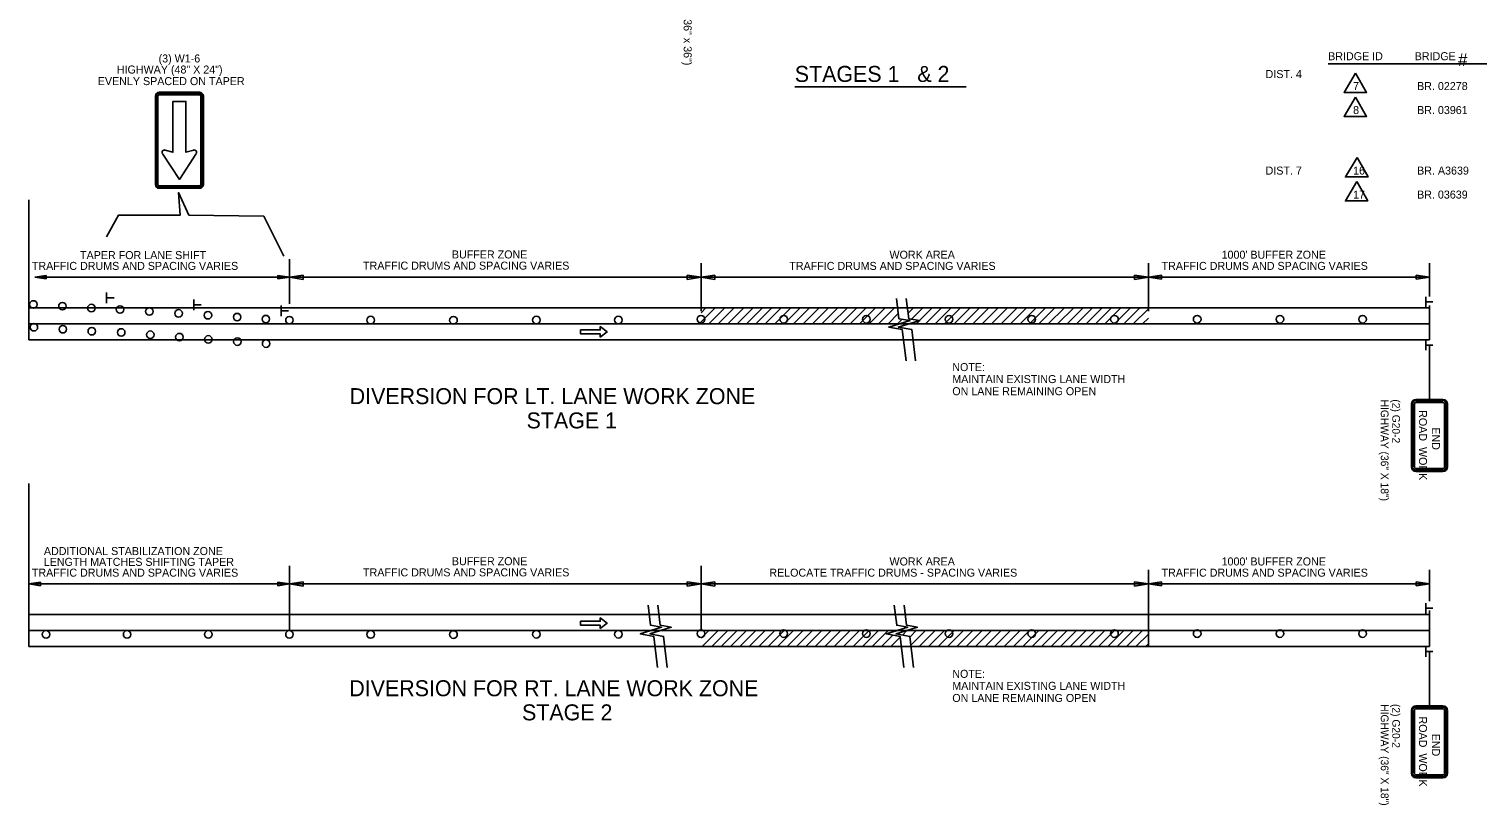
# Model space of a CAD drawing. Extents: x 1930579 to 1937521, y 596183 to 597566.
# Drawn here: x 1935116 to 1936202, y 596334 to 596916 of the extents above; entities that cross this region are included whole.
import ezdxf

# ---------------------------------------------------------------- set-up
doc = ezdxf.new("R2010")
doc.units = 0
for name, color, linetype in [('Default', 7, 'Continuous'), ('P_TC_Signs_Permanent', 7, 'Continuous'), ('P_TC_Signs_Temporary', 7, 'Continuous'), ('R_Annotation', 7, 'Continuous'), ('R_Striping', 7, 'Continuous')]:
    doc.layers.add(name, color=color, linetype=linetype)

msp = doc.modelspace()

# ---------------------------------------------------------------- linework, layer by layer
at = {"layer": 'Default'}
for p, q in [((1935690.4, 596872.5), (1935818.8, 596872.5)), ((1935116.2, 596787.6), (1935116.2, 596682.7)), ((1935311.5, 596743.1), (1935311.5, 596709.7)), ((1935620.1, 596740.1), (1935620.1, 596704.2)), ((1935955.5, 596740.1), (1935955.5, 596704.2)), ((1936166.2, 596740.1), (1936166.2, 596715.1)), ((1935120.5, 596729.6), (1935129.2, 596730.9)), ((1935311.5, 596729.6), (1935120.5, 596729.6)), ((1935129.2, 596728.3), (1935120.5, 596729.6)), ((1935129.2, 596730.9), (1935129.2, 596728.3)), ((1935302.8, 596728.3), (1935302.8, 596730.9)), ((1935302.8, 596730.9), (1935311.5, 596729.6)), ((1935311.5, 596729.6), (1935302.8, 596728.3)), ((1935620.1, 596729.6), (1935311.5, 596729.6)), ((1935311.6, 596729.6), (1935321.9, 596731.1)), ((1935321.9, 596728), (1935311.6, 596729.6)), ((1935321.9, 596731.1), (1935321.9, 596728)), ((1935609.8, 596728), (1935609.8, 596731.1)), ((1935609.8, 596731.1), (1935620.1, 596729.6)), ((1935620.1, 596729.6), (1935609.8, 596728)), ((1935620.1, 596729.6), (1935630.4, 596731.1)), ((1935955.5, 596729.6), (1935620.1, 596729.6)), ((1935630.4, 596728), (1935620.1, 596729.6)), ((1935630.4, 596731.1), (1935630.4, 596728)), ((1935945.2, 596728), (1935945.2, 596731.1)), ((1935945.2, 596731.1), (1935955.5, 596729.6)), ((1935955.5, 596729.6), (1935945.2, 596728)), ((1935955.5, 596729.6), (1935965.4, 596731.1)), ((1936166.2, 596729.6), (1935955.5, 596729.6)), ((1935965.4, 596728.1), (1935955.5, 596729.6)), ((1935965.4, 596731.1), (1935965.4, 596728.1)), ((1936156.3, 596728.1), (1936156.3, 596731.1)), ((1936156.3, 596731.1), (1936166.2, 596729.6)), ((1936156.3, 596728.1), (1936156.3, 596731.1)), ((1936156.3, 596731.1), (1936166.2, 596729.6)), ((1936166.2, 596729.6), (1936156.3, 596728.1)), ((1936166.2, 596729.6), (1936156.3, 596728.1)), ((1935174.4, 596710.2), (1935174.4, 596718.2)), ((1936166.2, 596706.7), (1935116.2, 596706.7)), ((1935174.5, 596714.2), (1935180, 596714.2)), ((1935239.8, 596704.8), (1935239.8, 596712.8)), ((1935239.9, 596708.8), (1935245.4, 596708.8)), ((1935305.4, 596700.3), (1935305.4, 596708.3)), ((1935305.5, 596704.3), (1935310.9, 596704.3)), ((1935618.8, 596694.7), (1935630.8, 596706.7)), ((1935620.1, 596703), (1935623.8, 596706.7)), ((1935625.9, 596694.7), (1935637.9, 596706.7)), ((1935633, 596694.7), (1935645, 596706.7)), ((1935640.1, 596694.7), (1935652.1, 596706.7)), ((1935647.1, 596694.7), (1935659.1, 596706.7)), ((1935654.2, 596694.7), (1935666.2, 596706.7)), ((1935661.3, 596694.7), (1935673.3, 596706.7)), ((1935668.3, 596694.7), (1935680.3, 596706.7)), ((1935675.4, 596694.7), (1935687.4, 596706.7)), ((1935682.5, 596694.7), (1935694.5, 596706.7)), ((1935689.5, 596694.7), (1935701.5, 596706.7)), ((1935696.6, 596694.7), (1935708.6, 596706.7)), ((1935703.7, 596694.7), (1935715.7, 596706.7)), ((1935710.8, 596694.7), (1935722.8, 596706.7)), ((1935717.8, 596694.7), (1935729.8, 596706.7)), ((1935724.9, 596694.7), (1935736.9, 596706.7)), ((1935732, 596694.7), (1935744, 596706.7)), ((1935739, 596694.7), (1935751, 596706.7)), ((1935746.1, 596694.7), (1935758.1, 596706.7)), ((1935753.2, 596694.7), (1935765.2, 596706.7)), ((1935775.3, 596702.6), (1935779.3, 596706.7)), ((1935777.9, 596698.2), (1935786.4, 596706.7)), ((1935783.9, 596697.1), (1935793.5, 596706.7)), ((1935788.5, 596694.7), (1935800.5, 596706.7)), ((1935795.6, 596694.7), (1935807.6, 596706.7)), ((1935802.7, 596694.7), (1935814.7, 596706.7)), ((1935809.8, 596694.7), (1935821.8, 596706.7)), ((1935816.8, 596694.7), (1935828.8, 596706.7)), ((1935823.9, 596694.7), (1935835.9, 596706.7)), ((1935831, 596694.7), (1935843, 596706.7)), ((1935838, 596694.7), (1935850, 596706.7)), ((1935845.1, 596694.7), (1935857.1, 596706.7)), ((1935852.2, 596694.7), (1935864.2, 596706.7)), ((1935859.3, 596694.7), (1935871.3, 596706.7)), ((1935866.3, 596694.7), (1935878.3, 596706.7)), ((1935873.4, 596694.7), (1935885.4, 596706.7)), ((1935880.5, 596694.7), (1935892.5, 596706.7)), ((1935887.5, 596694.7), (1935899.5, 596706.7)), ((1935894.6, 596694.7), (1935906.6, 596706.7)), ((1935901.7, 596694.7), (1935913.7, 596706.7)), ((1935908.8, 596694.7), (1935920.8, 596706.7)), ((1935915.8, 596694.7), (1935927.8, 596706.7)), ((1935922.9, 596694.7), (1935934.9, 596706.7)), ((1935930, 596694.7), (1935942, 596706.7)), ((1935937, 596694.7), (1935949, 596706.7)), ((1935944.1, 596694.7), (1935955.5, 596706)), ((1936163.5, 596714.9), (1936163.5, 596707.3)), ((1936163.6, 596711.1), (1936168.8, 596711.1)), ((1936166.2, 596708.4), (1936166.2, 596682.7)), ((1935116.2, 596694.7), (1936166.2, 596694.7)), ((1935760.3, 596694.7), (1935768, 596702.4)), ((1935767.3, 596694.7), (1935770.8, 596698.1)), ((1935781.5, 596694.7), (1935783.8, 596697)), ((1935951.2, 596694.7), (1935955.5, 596699)), ((1935116.2, 596682.7), (1935396.7, 596682.7)), ((1936166.2, 596682.7), (1935116.2, 596682.7)), ((1935380.8, 596682.7), (1935655.9, 596682.7)), ((1935593.2, 596682.7), (1935619.9, 596682.7)), ((1935619.9, 596682.7), (1935770.5, 596682.7)), ((1935778.2, 596682.7), (1935955.5, 596682.7)), ((1936163.5, 596682.4), (1936163.5, 596674.8)), ((1936163.6, 596678.6), (1936168.8, 596678.6)), ((1935116.2, 596574.9), (1935116.2, 596452.6)), ((1935311.5, 596513), (1935311.5, 596464.6)), ((1935620.1, 596513), (1935620.1, 596474.1)), ((1935620.1, 596513), (1935620.1, 596464.6)), ((1935955.5, 596510), (1935955.5, 596452.6)), ((1935955.5, 596510), (1935955.5, 596474.1)), ((1936166.2, 596510), (1936166.2, 596486.5)), ((1935116.2, 596499.5), (1935124.9, 596500.8)), ((1935311.5, 596499.5), (1935116.2, 596499.5)), ((1935124.9, 596498.2), (1935116.2, 596499.5)), ((1935124.9, 596500.8), (1935124.9, 596498.2)), ((1935302.8, 596498.2), (1935302.8, 596500.8)), ((1935302.8, 596500.8), (1935311.5, 596499.5)), ((1935311.5, 596499.5), (1935302.8, 596498.2)), ((1935620.1, 596499.5), (1935311.5, 596499.5)), ((1935311.6, 596499.5), (1935321.9, 596501)), ((1935321.9, 596497.9), (1935311.6, 596499.5)), ((1935321.9, 596501), (1935321.9, 596497.9)), ((1935609.8, 596497.9), (1935609.8, 596501)), ((1935609.8, 596501), (1935620.1, 596499.5)), ((1935620.1, 596499.5), (1935609.8, 596497.9)), ((1935620.1, 596499.5), (1935630.4, 596501)), ((1935955.5, 596499.5), (1935620.1, 596499.5)), ((1935630.4, 596497.9), (1935620.1, 596499.5)), ((1935630.4, 596501), (1935630.4, 596497.9)), ((1935945.2, 596497.9), (1935945.2, 596501)), ((1935945.2, 596501), (1935955.5, 596499.5)), ((1935955.5, 596499.5), (1935945.2, 596497.9)), ((1935955.5, 596499.5), (1935965.4, 596501)), ((1936166.2, 596499.5), (1935955.5, 596499.5)), ((1935965.4, 596498), (1935955.5, 596499.5)), ((1935965.4, 596501), (1935965.4, 596498)), ((1936156.3, 596498), (1936156.3, 596501)), ((1936156.3, 596501), (1936166.2, 596499.5)), ((1936156.3, 596498), (1936156.3, 596501)), ((1936156.3, 596501), (1936166.2, 596499.5)), ((1936166.2, 596499.5), (1936156.3, 596498)), ((1936166.2, 596499.5), (1936156.3, 596498)), ((1936166.2, 596476.6), (1935116.2, 596476.6)), ((1936163.5, 596485.1), (1936163.5, 596477.4)), ((1936163.6, 596481.3), (1936168.8, 596481.3)), ((1936166.2, 596479.5), (1936166.2, 596452.6)), ((1935116.2, 596464.6), (1936166.2, 596464.6)), ((1935620.1, 596458.8), (1935625.9, 596464.6)), ((1935621, 596452.6), (1935633, 596464.6)), ((1935628.1, 596452.6), (1935640.1, 596464.6)), ((1935635.1, 596452.6), (1935647.1, 596464.6)), ((1935642.2, 596452.6), (1935654.2, 596464.6)), ((1935649.3, 596452.6), (1935661.3, 596464.6)), ((1935656.3, 596452.6), (1935668.3, 596464.6)), ((1935663.4, 596452.6), (1935675.4, 596464.6)), ((1935670.5, 596452.6), (1935682.5, 596464.6)), ((1935677.5, 596452.6), (1935689.5, 596464.6)), ((1935684.6, 596452.6), (1935696.6, 596464.6)), ((1935691.7, 596452.6), (1935703.7, 596464.6)), ((1935698.8, 596452.6), (1935710.8, 596464.6)), ((1935705.8, 596452.6), (1935717.8, 596464.6)), ((1935712.9, 596452.6), (1935724.9, 596464.6)), ((1935720, 596452.6), (1935732, 596464.6)), ((1935727, 596452.6), (1935739, 596464.6)), ((1935734.1, 596452.6), (1935746.1, 596464.6)), ((1935741.2, 596452.6), (1935753.2, 596464.6)), ((1935748.3, 596452.6), (1935760.3, 596464.6)), ((1935755.3, 596452.6), (1935764, 596461.2)), ((1935762.4, 596452.6), (1935769.4, 596459.6)), ((1935771.1, 596461.2), (1935774.4, 596464.6)), ((1935776.5, 596452.6), (1935788.5, 596464.6)), ((1935776.6, 596459.7), (1935781.5, 596464.6)), ((1935783.6, 596452.6), (1935795.6, 596464.6)), ((1935790.7, 596452.6), (1935802.7, 596464.6)), ((1935797.8, 596452.6), (1935809.8, 596464.6)), ((1935804.8, 596452.6), (1935816.8, 596464.6)), ((1935811.9, 596452.6), (1935823.9, 596464.6)), ((1935819, 596452.6), (1935831, 596464.6)), ((1935826, 596452.6), (1935838, 596464.6)), ((1935833.1, 596452.6), (1935845.1, 596464.6)), ((1935840.2, 596452.6), (1935852.2, 596464.6)), ((1935847.3, 596452.6), (1935859.3, 596464.6)), ((1935854.3, 596452.6), (1935866.3, 596464.6)), ((1935861.4, 596452.6), (1935873.4, 596464.6)), ((1935868.5, 596452.6), (1935880.5, 596464.6)), ((1935875.5, 596452.6), (1935887.5, 596464.6)), ((1935882.6, 596452.6), (1935894.6, 596464.6)), ((1935889.7, 596452.6), (1935901.7, 596464.6)), ((1935896.8, 596452.6), (1935908.8, 596464.6)), ((1935903.8, 596452.6), (1935915.8, 596464.6)), ((1935910.9, 596452.6), (1935922.9, 596464.6)), ((1935918, 596452.6), (1935930, 596464.6)), ((1935925, 596452.6), (1935937, 596464.6)), ((1935932.1, 596452.6), (1935944.1, 596464.6)), ((1935939.2, 596452.6), (1935951.2, 596464.6)), ((1935946.2, 596452.6), (1935955.5, 596461.8)), ((1935953.3, 596452.6), (1935955.5, 596454.7)), ((1935116.2, 596452.6), (1935396.7, 596452.6)), ((1936166.2, 596452.6), (1935116.2, 596452.6)), ((1935380.8, 596452.6), (1935655.9, 596452.6)), ((1935593.2, 596452.6), (1935619.9, 596452.6)), ((1935619.9, 596452.6), (1935770.5, 596452.6)), ((1935769.5, 596452.6), (1935770.1, 596453.2)), ((1935778.2, 596452.6), (1935955.5, 596452.6)), ((1936163.5, 596452.6), (1936163.5, 596444.9)), ((1936163.6, 596448.8), (1936168.8, 596448.8))]:
    msp.add_line(p, q, dxfattribs=at)
for points in [[(1935766.6, 596713.6), (1935768.5, 596698.5), (1935776.8, 596697.1), (1935760.8, 596692.2), (1935770.9, 596690.3), (1935773.8, 596666.9)], [(1935773.9, 596713.6), (1935775.8, 596698.5), (1935784.1, 596697.1), (1935768, 596692.2), (1935778.2, 596690.3), (1935781, 596666.9)], [(1935580.4, 596483.5), (1935582.3, 596468.5), (1935590.5, 596467), (1935574.5, 596462.1), (1935584.7, 596460.2), (1935587.5, 596436.8)], [(1935587.7, 596483.5), (1935589.5, 596468.5), (1935597.8, 596467), (1935581.8, 596462.1), (1935592, 596460.2), (1935594.8, 596436.8)], [(1935765, 596483.5), (1935766.9, 596468.5), (1935775.1, 596467), (1935759.1, 596462.1), (1935769.3, 596460.2), (1935772.1, 596436.8)], [(1935772.3, 596483.5), (1935774.2, 596468.5), (1935782.4, 596467), (1935766.4, 596462.1), (1935776.6, 596460.2), (1935779.4, 596436.8)]]:
    msp.add_lwpolyline(points, dxfattribs=at)
for centre, radius in [((1935119.5, 596709.2), 2.81), ((1935141.3, 596707.9), 2.81), ((1935163, 596706.5), 2.81), ((1935184.5, 596705.4), 2.81), ((1935206.5, 596703.9), 2.81), ((1935228.4, 596702.5), 2.81), ((1935119.9, 596692.1), 2.81), ((1935141.6, 596690.6), 2.81), ((1935250.4, 596701.1), 2.81), ((1935272.3, 596699.7), 2.81), ((1935293.8, 596698.2), 2.81), ((1935311.5, 596697.4), 2.81), ((1935372.4, 596697.4), 2.87), ((1935434.5, 596697.3), 2.87), ((1935496.7, 596697.5), 2.87), ((1935558.2, 596697.5), 2.87), ((1935620.1, 596698.1), 2.87), ((1935682.1, 596698.1), 2.87), ((1935744.1, 596698.1), 2.87), ((1935806.1, 596698.1), 2.87), ((1935868.1, 596698.1), 2.87), ((1935930.1, 596698.1), 2.87), ((1935992.1, 596698.1), 2.87), ((1936054.1, 596698.1), 2.87), ((1936116.1, 596698.1), 2.87), ((1935163.3, 596689.1), 2.81), ((1935185.4, 596688.2), 2.81), ((1935207.2, 596686.5), 2.81), ((1935229, 596684.7), 2.81), ((1935250.7, 596683), 2.81), ((1935272.5, 596681.3), 2.81), ((1935294, 596679.8), 2.81), ((1935129, 596461.7), 2.81), ((1935189.8, 596461.7), 2.81), ((1935250.7, 596461.7), 2.81), ((1935311.5, 596461.7), 2.81), ((1935372.4, 596461.7), 2.87), ((1935434.5, 596461.6), 2.87), ((1935496.7, 596461.8), 2.87), ((1935558.2, 596461.8), 2.87), ((1935620.1, 596462.3), 2.87), ((1935682.1, 596462.3), 2.87), ((1935744.1, 596462.3), 2.87), ((1935806.1, 596462.3), 2.87), ((1935868.1, 596462.3), 2.87), ((1935930.1, 596462.3), 2.87), ((1935992.1, 596462.3), 2.87), ((1936054.1, 596462.3), 2.87), ((1936116.1, 596462.3), 2.87)]:
    msp.add_circle(centre, radius, dxfattribs=at)
at = {"layer": 'P_TC_Signs_Permanent'}
for p, q in [((1935244.2, 596868.3), (1935213.8, 596868.3)), ((1935244.2, 596867.5), (1935213.8, 596867.5)), ((1935211, 596865.5), (1935211, 596799.1)), ((1935211.8, 596865.5), (1935211.8, 596799.1)), ((1935212.9, 596865.5), (1935212.9, 596799.1)), ((1935244.2, 596866.4), (1935213.8, 596866.4)), ((1935245.1, 596799.1), (1935245.1, 596865.5)), ((1935246.3, 596799.1), (1935246.3, 596865.5)), ((1935247, 596799.1), (1935247, 596865.5)), ((1935213.8, 596798.2), (1935244.2, 596798.2)), ((1935213.8, 596797), (1935244.2, 596797)), ((1935213.8, 596796.3), (1935244.2, 596796.3))]:
    msp.add_line(p, q, dxfattribs=at)
for points in [[(1935239.7, 596825), (1935233.9, 596823.3), (1935233.9, 596861.5), (1935224.1, 596861.5), (1935224.1, 596823.3), (1935218.4, 596825)], [(1935216.6, 596822), (1935229, 596803), (1935241.4, 596822)]]:
    msp.add_lwpolyline(points, dxfattribs=at)
for centre, radius, start, end in [((1935213.8, 596865.5), 2.81, 90, 180), ((1935213.8, 596865.5), 2.06, 90, 180), ((1935244.2, 596865.5), 2.81, 360, 90), ((1935244.2, 596865.5), 2.06, 360, 90), ((1935213.8, 596865.5), 0.938, 90, 180), ((1935244.2, 596865.5), 0.937, 360, 90), ((1935217.9, 596823.3), 1.8, 74.0309, 213.4755), ((1935240.1, 596823.3), 1.76, 326.5994, 105.9691), ((1935153.8, 596780.9), 75, 33.2286, 33.4755), ((1935304.2, 596781), 75, 146.5994, 146.857), ((1935213.8, 596799.1), 2.81, 180, 270), ((1935213.8, 596799.1), 2.06, 180, 270), ((1935213.8, 596799.1), 0.938, 180, 270), ((1935244.2, 596799.1), 2.81, 270, 360), ((1935244.2, 596799.1), 2.06, 270, 360), ((1935244.2, 596799.1), 0.938, 270, 360)]:
    msp.add_arc(centre, radius, start, end, dxfattribs=at)
at = {"layer": 'P_TC_Signs_Temporary'}
for p, q in [((1936152.7, 596634.6), (1936152.7, 596587.3)), ((1936153.7, 596634.6), (1936153.7, 596587.3)), ((1936155, 596634.6), (1936155, 596587.3)), ((1936176.4, 596638), (1936156.1, 596638)), ((1936176.4, 596637), (1936156.1, 596637)), ((1936176.4, 596635.7), (1936156.1, 596635.7)), ((1936177.5, 596587.3), (1936177.5, 596634.6)), ((1936178.8, 596587.3), (1936178.8, 596634.6)), ((1936179.7, 596587.3), (1936179.7, 596634.6)), ((1936156.1, 596586.2), (1936176.4, 596586.2)), ((1936156.1, 596584.9), (1936176.4, 596584.9)), ((1936156.1, 596584), (1936176.4, 596584)), ((1936152.7, 596404.7), (1936152.7, 596357.5)), ((1936153.7, 596404.7), (1936153.7, 596357.5)), ((1936155, 596404.7), (1936155, 596357.5)), ((1936176.4, 596408.1), (1936156.1, 596408.1)), ((1936176.4, 596407.2), (1936156.1, 596407.2)), ((1936176.4, 596405.9), (1936156.1, 596405.9)), ((1936177.5, 596357.5), (1936177.5, 596404.7)), ((1936178.8, 596357.5), (1936178.8, 596404.7)), ((1936179.7, 596357.5), (1936179.7, 596404.7)), ((1936156.1, 596356.4), (1936176.4, 596356.4)), ((1936156.1, 596355.1), (1936176.4, 596355.1)), ((1936156.1, 596354.1), (1936176.4, 596354.1))]:
    msp.add_line(p, q, dxfattribs=at)
for centre, radius, start, end in [((1936156.1, 596634.6), 3.37, 90, 180), ((1936156.1, 596634.6), 2.44, 90, 180), ((1936156.1, 596634.6), 1.13, 90, 180), ((1936176.4, 596634.6), 3.37, 360, 90), ((1936176.4, 596634.6), 2.44, 360, 90), ((1936176.4, 596634.6), 1.13, 360, 90), ((1936156.1, 596587.3), 3.37, 180, 270), ((1936156.1, 596587.3), 2.44, 180, 270), ((1936156.1, 596587.3), 1.13, 180, 270), ((1936176.4, 596587.3), 2.44, 270, 360), ((1936176.4, 596587.3), 1.13, 270, 360), ((1936176.4, 596587.3), 3.38, 270, 360), ((1936156.1, 596404.7), 3.37, 90, 180), ((1936156.1, 596404.7), 2.44, 90, 180), ((1936156.1, 596404.7), 1.13, 90, 180), ((1936176.4, 596404.7), 3.37, 360, 90), ((1936176.4, 596404.7), 2.44, 360, 90), ((1936176.4, 596404.7), 1.13, 360, 90), ((1936156.1, 596357.5), 3.37, 180, 270), ((1936156.1, 596357.5), 2.44, 180, 270), ((1936156.1, 596357.5), 1.13, 180, 270), ((1936176.4, 596357.5), 2.44, 270, 360), ((1936176.4, 596357.5), 1.13, 270, 360), ((1936176.4, 596357.5), 3.38, 270, 360)]:
    msp.add_arc(centre, radius, start, end, dxfattribs=at)
at = {"layer": 'R_Annotation'}
for p, q in [((1936090.3, 596889.7), (1936637.5, 596889.7)), ((1936166.2, 596638), (1936166.2, 596678.6)), ((1936166.2, 596408.1), (1936166.2, 596448.8))]:
    msp.add_line(p, q, dxfattribs=at)
for points in [[(1936110.9, 596882.7), (1936102.2, 596868.2), (1936119.1, 596868.2), (1936110.9, 596882.7)], [(1936110.9, 596864.7), (1936102.2, 596850.2), (1936119.1, 596850.2), (1936110.9, 596864.7)], [(1936112, 596819.3), (1936103.3, 596804.8), (1936120.2, 596804.8), (1936112, 596819.3)], [(1935174.4, 596759.9), (1935183.4, 596776.2), (1935229.6, 596776.2), (1935228.4, 596793.1), (1935236.2, 596776.2), (1935292.3, 596775.4), (1935307.3, 596745.3)], [(1936111.9, 596801.3), (1936103.2, 596786.8), (1936120, 596786.8), (1936111.9, 596801.3)]]:
    msp.add_lwpolyline(points, dxfattribs=at)
at = {"layer": 'R_Striping'}
for points in [[(1935544.5, 596684.6), (1935549.7, 596688.6), (1935544.5, 596692.6), (1935544.5, 596690.1), (1935529.8, 596690.1), (1935529.8, 596687.1), (1935544.5, 596687.1)], [(1935544.5, 596466), (1935549.7, 596470), (1935544.5, 596474), (1935544.5, 596471.5), (1935529.8, 596471.5), (1935529.8, 596468.5), (1935544.5, 596468.5)]]:
    msp.add_lwpolyline(points, close=True, dxfattribs=at)

# ---------------------------------------------------------------- texts
at = {"layer": 'Default'}
for s, height, p in [('STAGES 1   & 2', 12, (1935690.4, 596876.1)), ('TAPER FOR LANE SHIFT', 6, (1935154.5, 596743.2)), ('BUFFER ZONE', 6, (1935433.3, 596743.7)), ('WORK AREA', 6, (1935761.4, 596743.5)), ("1000' BUFFER ZONE", 6, (1936010.4, 596743.5)), ('TRAFFIC DRUMS AND SPACING VARIES', 6, (1935118.4, 596735.1)), ('TRAFFIC DRUMS AND SPACING VARIES', 6, (1935366.7, 596735.3)), ('TRAFFIC DRUMS AND SPACING VARIES', 6, (1935686.3, 596735.1)), ('TRAFFIC DRUMS AND SPACING VARIES', 6, (1935965.4, 596735.1)), ('DIVERSION FOR LT. LANE WORK ZONE', 12, (1935356.7, 596634.4)), ('STAGE 1', 12, (1935489.3, 596616.2)), ('ADDITIONAL STABILIZATION ZONE', 6, (1935127.4, 596521.2)), ('BUFFER ZONE', 6, (1935433.3, 596513.6)), ('TRAFFIC DRUMS AND SPACING VARIES', 6, (1935118.4, 596505)), ('LENGTH MATCHES SHIFTING TAPER', 6, (1935127.3, 596513.1)), ('TRAFFIC DRUMS AND SPACING VARIES', 6, (1935366.7, 596505.2)), ('RELOCATE TRAFFIC DRUMS - SPACING VARIES', 6, (1935671.3, 596505)), ('WORK AREA', 6, (1935761.4, 596513.4)), ('TRAFFIC DRUMS AND SPACING VARIES', 6, (1935965.4, 596505)), ("1000' BUFFER ZONE", 6, (1936010.4, 596513.4)), ('DIVERSION FOR RT. LANE WORK ZONE', 12, (1935356.4, 596415.3)), ('STAGE 2', 12, (1935485.9, 596397.2))]:
    msp.add_text(s, height=height, rotation=360, dxfattribs=at).set_placement(p)
at = {"layer": 'P_TC_Signs_Temporary'}
for s, p in [('ROAD  WORK', (1936158.4, 596629.9)), ('END', (1936168.1, 596617)), ('ROAD  WORK', (1936158.4, 596400.1)), ('END', (1936168.1, 596387.2))]:
    msp.add_text(s, height=6, rotation=270, dxfattribs=at).set_placement(p)
at = {"layer": 'R_Annotation'}
for s, height, rotation, p in [('HIGHWAY (36" x 36")', 6, 270, (1935607.1, 596966.4)), ('HIGHWAY (48" X 24")', 6, 0.0075, (1935182.1, 596882.4)), ('(3) W1-6', 6, 0.0075, (1935213.4, 596890.7)), ('BRIDGE ID', 6, 360, (1936090.3, 596892.4)), ('BRIDGE ', 6, 360, (1936155.2, 596892.4)), ('#', 9.6, 360, (1936187.7, 596888.1)), ('EVENLY SPACED ON TAPER', 6, 0.0075, (1935167.8, 596873.7)), ('DIST. 4', 6, 360, (1936043.4, 596879)), ('7', 6, 360, (1936109, 596870)), ('BR. 02278', 6, 360, (1936157, 596870)), ('8', 6, 360, (1936109, 596852)), ('BR. 03961', 6, 360, (1936157, 596852)), ('DIST. 7', 6, 360, (1936043.4, 596806.6)), ('16', 6, 360, (1936109, 596806.6)), ('BR. A3639', 6, 360, (1936157, 596806.6)), ('17', 6, 360, (1936109, 596788.6)), ('BR. 03639', 6, 360, (1936157, 596788.6)), ('NOTE:', 6, 360, (1935808.5, 596659.2)), ('MAINTAIN EXISTING LANE WIDTH', 6, 360, (1935808.5, 596650.2)), ('ON LANE REMAINING OPEN', 6, 360, (1935808.5, 596641.1)), ('HIGHWAY (36" X 18")', 5.76, 270, (1936129.8, 596637.8)), ('(2) G20-2', 5.76, 270, (1936138.4, 596638)), ('NOTE:', 6, 360, (1935808.5, 596429.1)), ('MAINTAIN EXISTING LANE WIDTH', 6, 360, (1935808.5, 596420.1)), ('ON LANE REMAINING OPEN', 6, 360, (1935808.5, 596411)), ('HIGHWAY (36" X 18")', 5.76, 270, (1936129.8, 596409.3)), ('(2) G20-2', 5.76, 270, (1936138.4, 596409.5))]:
    msp.add_text(s, height=height, rotation=rotation, dxfattribs=at).set_placement(p)

doc.saveas('drawing.dxf')
